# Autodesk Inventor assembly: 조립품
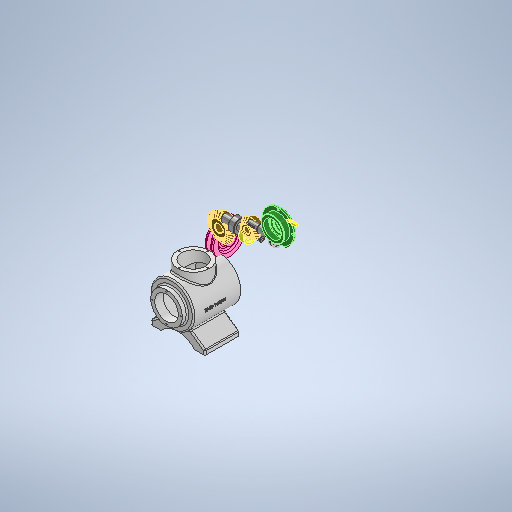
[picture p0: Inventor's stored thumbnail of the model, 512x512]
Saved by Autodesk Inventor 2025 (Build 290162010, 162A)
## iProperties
Created: 2024-07
Part Number: 조립품
Document SubType Name: Assembly
Designer: 학생
Author: 학생
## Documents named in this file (15)
- C:\Users\학생\Desktop\740709V1001\조립품.iam
- C:\Users\학생\Desktop\740709V1001\V-벨트풀리\V-벨트풀리.ipt
- C:\Users\학생\Desktop\740709V1001\메인 베벨기어\메인 베벨기어.ipt
- C:\Users\학생\Desktop\740709V1001\메인 축\메인 축.ipt
- C:\Users\학생\Desktop\740709V1001\베어링 6203\베어링 6203.ipt
- C:\Users\학생\Desktop\740709V1001\볼트 M4 x 10\볼트 M4 x 10.ipt
- C:\Users\학생\Desktop\740709V1001\서브 베벨기어\서브 베벨기어.ipt
- C:\Users\학생\Desktop\740709V1001\서브 축\서브 축.ipt
- C:\Users\학생\Desktop\740709V1001\오일실 17 x 32 x 8\오일실 17 x 32 x 8.ipt
- C:\Users\학생\Desktop\740709V1001\와셔 4 x 16\와셔 4 x 16.ipt
- C:\Users\학생\Desktop\740709V1001\육각볼트 M4 x 8\육각볼트 M4 x 8.ipt
- C:\Users\학생\Desktop\740709V1001\커버\커버.ipt
- C:\Users\학생\Desktop\740709V1001\키 4 x 4 x 14\키 4 x 4 x 14.ipt
- C:\Users\학생\Desktop\740709V1001\키 5 x 5 x 14\키 5 x 5 x 14.ipt
- C:\Users\학생\Desktop\740709V1001\본체.ipt
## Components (1 placed, 1 different names)
1. V-벨트풀리:1
